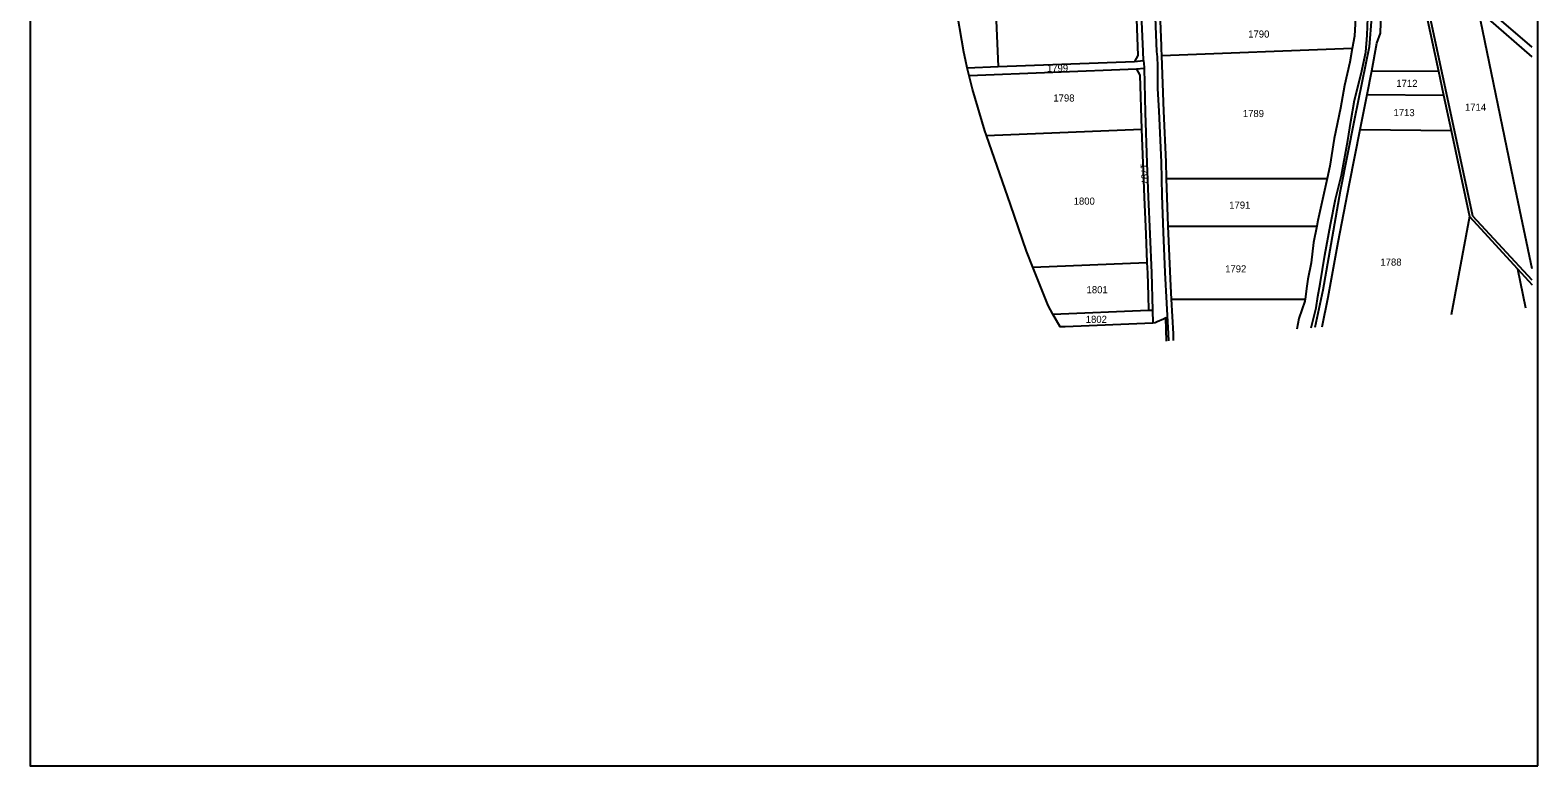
# Model space of a CAD drawing. Extents: x -584305 to -582773, y -1166873 to -1164718.
# Drawn here: x -584305 to -582820, y -1166873 to -1166148 of the extents above; entities that cross this region are included whole.
import ezdxf

# ---------------------------------------------------------------- set-up
doc = ezdxf.new("R2010")
doc.units = 0
for name, color, linetype in [('_Rám HC11-R', 7, 'Continuous'), ('Hranice parcel', 7, 'Continuous'), ('Parcelní čísla', 7, 'Continuous')]:
    doc.layers.add(name, color=color, linetype=linetype)

msp = doc.modelspace()

# ---------------------------------------------------------------- linework, layer by layer
at = {"layer": '_Rám HC11-R'}
msp.add_lwpolyline([(-582820, -1166873.1), (-582820, -1164773.1), (-584305, -1164773.1), (-584305, -1166873.1), (-582820, -1166873.1)], dxfattribs=at)
at = {"layer": 'Hranice parcel'}
for p, q in [((-583002.8, -1166166.4), (-583190.3, -1166173.7)), ((-583382, -1166185.3), (-583383.9, -1166177.6)), ((-583382, -1166185.3), (-583351.6, -1166184)), ((-583380.1, -1166193.3), (-583382, -1166185.3)), ((-583351.6, -1166184), (-583217.4, -1166179.2)), ((-583217.4, -1166179.2), (-583208.6, -1166178.2)), ((-583215.3, -1166186.6), (-583380.1, -1166193.3)), ((-583207.8, -1166186.2), (-583215.3, -1166186.6)), ((-582988.2, -1166211.6), (-582983.7, -1166188.2)), ((-582983.7, -1166188.2), (-582917.9, -1166188.7)), ((-582917.9, -1166188.7), (-582912.8, -1166212.2)), ((-582995.1, -1166246.2), (-582988.2, -1166211.6)), ((-582988.2, -1166211.6), (-582912.8, -1166212.2)), ((-582912.8, -1166212.2), (-582905.4, -1166247)), ((-583363.2, -1166251.9), (-583210.3, -1166245.7)), ((-582995.1, -1166246.2), (-582905.4, -1166247)), ((-582905.4, -1166247), (-582887.2, -1166331.9)), ((-583185.7, -1166294.4), (-583027.4, -1166294.4)), ((-583184.3, -1166341.3), (-583185.7, -1166294.4)), ((-582887.2, -1166331.9), (-582840.2, -1166383.3)), ((-583184.3, -1166341.3), (-583037.8, -1166341.3)), ((-583317.4, -1166381.9), (-583205, -1166377.3)), ((-582840.2, -1166383.3), (-582825.7, -1166399.1)), ((-583180.7, -1166413.2), (-583049.3, -1166413.2)), ((-583297.6, -1166428.1), (-583203.5, -1166424.2)), ((-583203.5, -1166424.2), (-583199.5, -1166424.1)), ((-583199.5, -1166424.1), (-583199.1, -1166436.8)), ((-583197.1, -1166436.7), (-583199.1, -1166436.8))]:
    msp.add_line(p, q, dxfattribs=at)
for points in [[(-583012.4, -1165748.2), (-583016.5, -1165758.9), (-583017, -1165788.4), (-583015.4, -1165822), (-583013.4, -1165843.2), (-583011.3, -1165864.4), (-582999.8, -1165958.9), (-582997.1, -1165981.8), (-582992.8, -1166018.3), (-582991.3, -1166032), (-582990, -1166050), (-582988.6, -1166068.1), (-582987.3, -1166081.4), (-582986, -1166094.7), (-582983.8, -1166135.7), (-582986.3, -1166164.8), (-583000.5, -1166235.8), (-583014.7, -1166306.9), (-583031.8, -1166404.6), (-583039.6, -1166441.1)], [(-583231.4, -1165901.9), (-583227.2, -1166006.9), (-583220.6, -1166009.4), (-583218.1, -1166066), (-583213.9, -1166173.2), (-583217.4, -1166179.2)], [(-583363.6, -1165907.4), (-583355.5, -1166093.1), (-583351.6, -1166184)], [(-582983.7, -1166188.2), (-582978.5, -1166161.2), (-582974.9, -1166151.1), (-582974.3, -1166130.6), (-582977.2, -1166120.6), (-582982.5, -1166063.2), (-582987.8, -1166005.9), (-582992.5, -1165964.7), (-582996.5, -1165931.9)], [(-582940.9, -1165931.9), (-582942.8, -1165992.4), (-582945, -1166061.9), (-582917.9, -1166188.7)], [(-583208.6, -1166178.2), (-583208.9, -1166169.2), (-583210.6, -1166124.8), (-583213.1, -1166072.8), (-583214, -1166035.8), (-583215.5, -1166006.5)], [(-583203.1, -1166002.3), (-583201.5, -1166034.7), (-583199.8, -1166073), (-583198.4, -1166093.9), (-583197.5, -1166118.9), (-583195.5, -1166169.3), (-583195.1, -1166174.6), (-583194.7, -1166183.8), (-583194.7, -1166188.4), (-583194.6, -1166205.8), (-583193.3, -1166228.2), (-583191.2, -1166278.2), (-583190.3, -1166311.3), (-583189.2, -1166347.4), (-583187.3, -1166387.1), (-583184, -1166447.4), (-583183.9, -1166454.5)], [(-582825.7, -1166394.7), (-582884, -1166331.4), (-582901.1, -1166251.7), (-582938.5, -1166076.9)], [(-582825.7, -1166165.1), (-582858.2, -1166137), (-582898.7, -1166102.1)], [(-583383.9, -1166177.6), (-583385.5, -1166169.9), (-583393.6, -1166121.9)], [(-583000.3, -1166124.4), (-582999.8, -1166134.5), (-583000.1, -1166141.9), (-583000.6, -1166154.3), (-583002.8, -1166166.4)], [(-583190.3, -1166173.7), (-583190.6, -1166166.4), (-583190.7, -1166163.7), (-583191.6, -1166139.1)], [(-583043.3, -1166441.5), (-583038.4, -1166421.8), (-583036.6, -1166410.6), (-583034.5, -1166398.2), (-583029.7, -1166369.9), (-583024.3, -1166339.7), (-583019.3, -1166314.9), (-583013.4, -1166291.3), (-583007.1, -1166257.1), (-583004.3, -1166238.2), (-583000.5, -1166217.2), (-582994.1, -1166191.4), (-582989.4, -1166169.9), (-582988.1, -1166153.2), (-582987.5, -1166136.1)], [(-582825.7, -1166383.4), (-582841.9, -1166305.3), (-582878.6, -1166128.5)], [(-582825.7, -1166174.6), (-582868.6, -1166137.1), (-582878.6, -1166128.5)], [(-583002.8, -1166166.4), (-583005.2, -1166179.8), (-583010.6, -1166202.7), (-583014.5, -1166225.2), (-583020.6, -1166255.1), (-583025, -1166282.2), (-583027.4, -1166294.4)], [(-583208.6, -1166178.2), (-583207.8, -1166184.7), (-583207.8, -1166186.2)], [(-583185.7, -1166294.4), (-583186.2, -1166278.1), (-583188.3, -1166228), (-583190.3, -1166173.7)], [(-583363.2, -1166251.9), (-583364.7, -1166247.4), (-583377, -1166206.4), (-583380.1, -1166193.3)], [(-583215.3, -1166186.6), (-583212.1, -1166192.5), (-583210.3, -1166245.7)], [(-583207.8, -1166186.2), (-583206.8, -1166229.5), (-583205.2, -1166279.2), (-583203.9, -1166312.5), (-583202.2, -1166349.2), (-583200.6, -1166387.4), (-583199.5, -1166424.1)], [(-583317.4, -1166381.9), (-583323.8, -1166365.9), (-583339.5, -1166320.2), (-583363.2, -1166251.9)], [(-583210.3, -1166245.7), (-583209.2, -1166279.3), (-583207.9, -1166312.7), (-583206.2, -1166349.4), (-583205, -1166377.3)], [(-583032.5, -1166440.5), (-583026.4, -1166411.2), (-583016.6, -1166357.3), (-583005.4, -1166299.2), (-582995.1, -1166246.2)], [(-583027.4, -1166294.4), (-583036.7, -1166335.7), (-583037.8, -1166341.3)], [(-582887.2, -1166331.9), (-582890.8, -1166351.4), (-582905.5, -1166428.7)], [(-583180.7, -1166413.2), (-583181.4, -1166400.5), (-583184.3, -1166341.3)], [(-583037.8, -1166341.3), (-583041.1, -1166357.6), (-583043.2, -1166377.5), (-583046.6, -1166393.7), (-583047.6, -1166400.5), (-583049.3, -1166413.2)], [(-583205, -1166377.3), (-583204.6, -1166387.6), (-583203.9, -1166409.7), (-583203.5, -1166424.2)], [(-583297.6, -1166428.1), (-583302.3, -1166419.6), (-583317.4, -1166381.9)], [(-582840.2, -1166383.3), (-582832.2, -1166421.8)], [(-583178.9, -1166454.1), (-583179, -1166447.4), (-583180.7, -1166413.2)], [(-583049.3, -1166413.2), (-583049.6, -1166415.2), (-583055.5, -1166432.2), (-583057.3, -1166442.8)], [(-583199.1, -1166436.8), (-583285.7, -1166440.6), (-583290.5, -1166440.7), (-583297.6, -1166428.1)], [(-583185.9, -1166454.7), (-583186.4, -1166431.8), (-583188.7, -1166432.9), (-583195, -1166435.7), (-583197.1, -1166436.7)]]:
    msp.add_lwpolyline(points, dxfattribs=at)

# ---------------------------------------------------------------- texts
at = {"layer": 'Parcelní čísla'}
for s, p in [('1790', (-583105.3, -1166155.6)), ('1799', (-583303.5, -1166189.2)), ('1712', (-582959.4, -1166204.2)), ('1798', (-583297.2, -1166218.6)), ('1789', (-583110.6, -1166233.9)), ('1713', (-582962.2, -1166233)), ('1714', (-582891.8, -1166227.7)), ('1800', (-583277.2, -1166320.2)), ('1791', (-583124, -1166324.1)), ('1788', (-582975.1, -1166380.3)), ('1792', (-583128, -1166386.9)), ('1801', (-583264.5, -1166407.5)), ('1802', (-583265.3, -1166436.7))]:
    msp.add_text(s, height=7, dxfattribs=at).set_placement(p)
msp.add_text('1797', height=7, rotation=273, dxfattribs=at).set_placement((-583211.3, -1166279.7))

doc.saveas('drawing.dxf')
